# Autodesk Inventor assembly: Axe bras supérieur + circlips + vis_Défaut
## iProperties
Shininess: 64.0
Length Units: 11269
Angle Units: 11279
Time Units: 11290
Mass Units: 11283
Length Display Precision: 3
Angle Display Precision: 2
Compacted: True
Created: 2006-11
Part Number: Axe bras supérieur + circlips + vis_Défaut
Document SubType Name: Assembly
Designer: profs_sti
Density: 0.0
Volumn: 0.0
Area: 0.0
PropertySet Name: Model Information
Control State: 0
Master: False
Checked Out: False
Author: profs_sti
